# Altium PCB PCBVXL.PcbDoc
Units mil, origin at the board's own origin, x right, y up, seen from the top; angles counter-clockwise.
Board outline 3800 x 3375 mil, 2 copper layers (Top Layer, Bottom Layer); 16 components, 11 nets, 91 pads, 0 vias.
Unrouted connection lines stored in the file: 1.
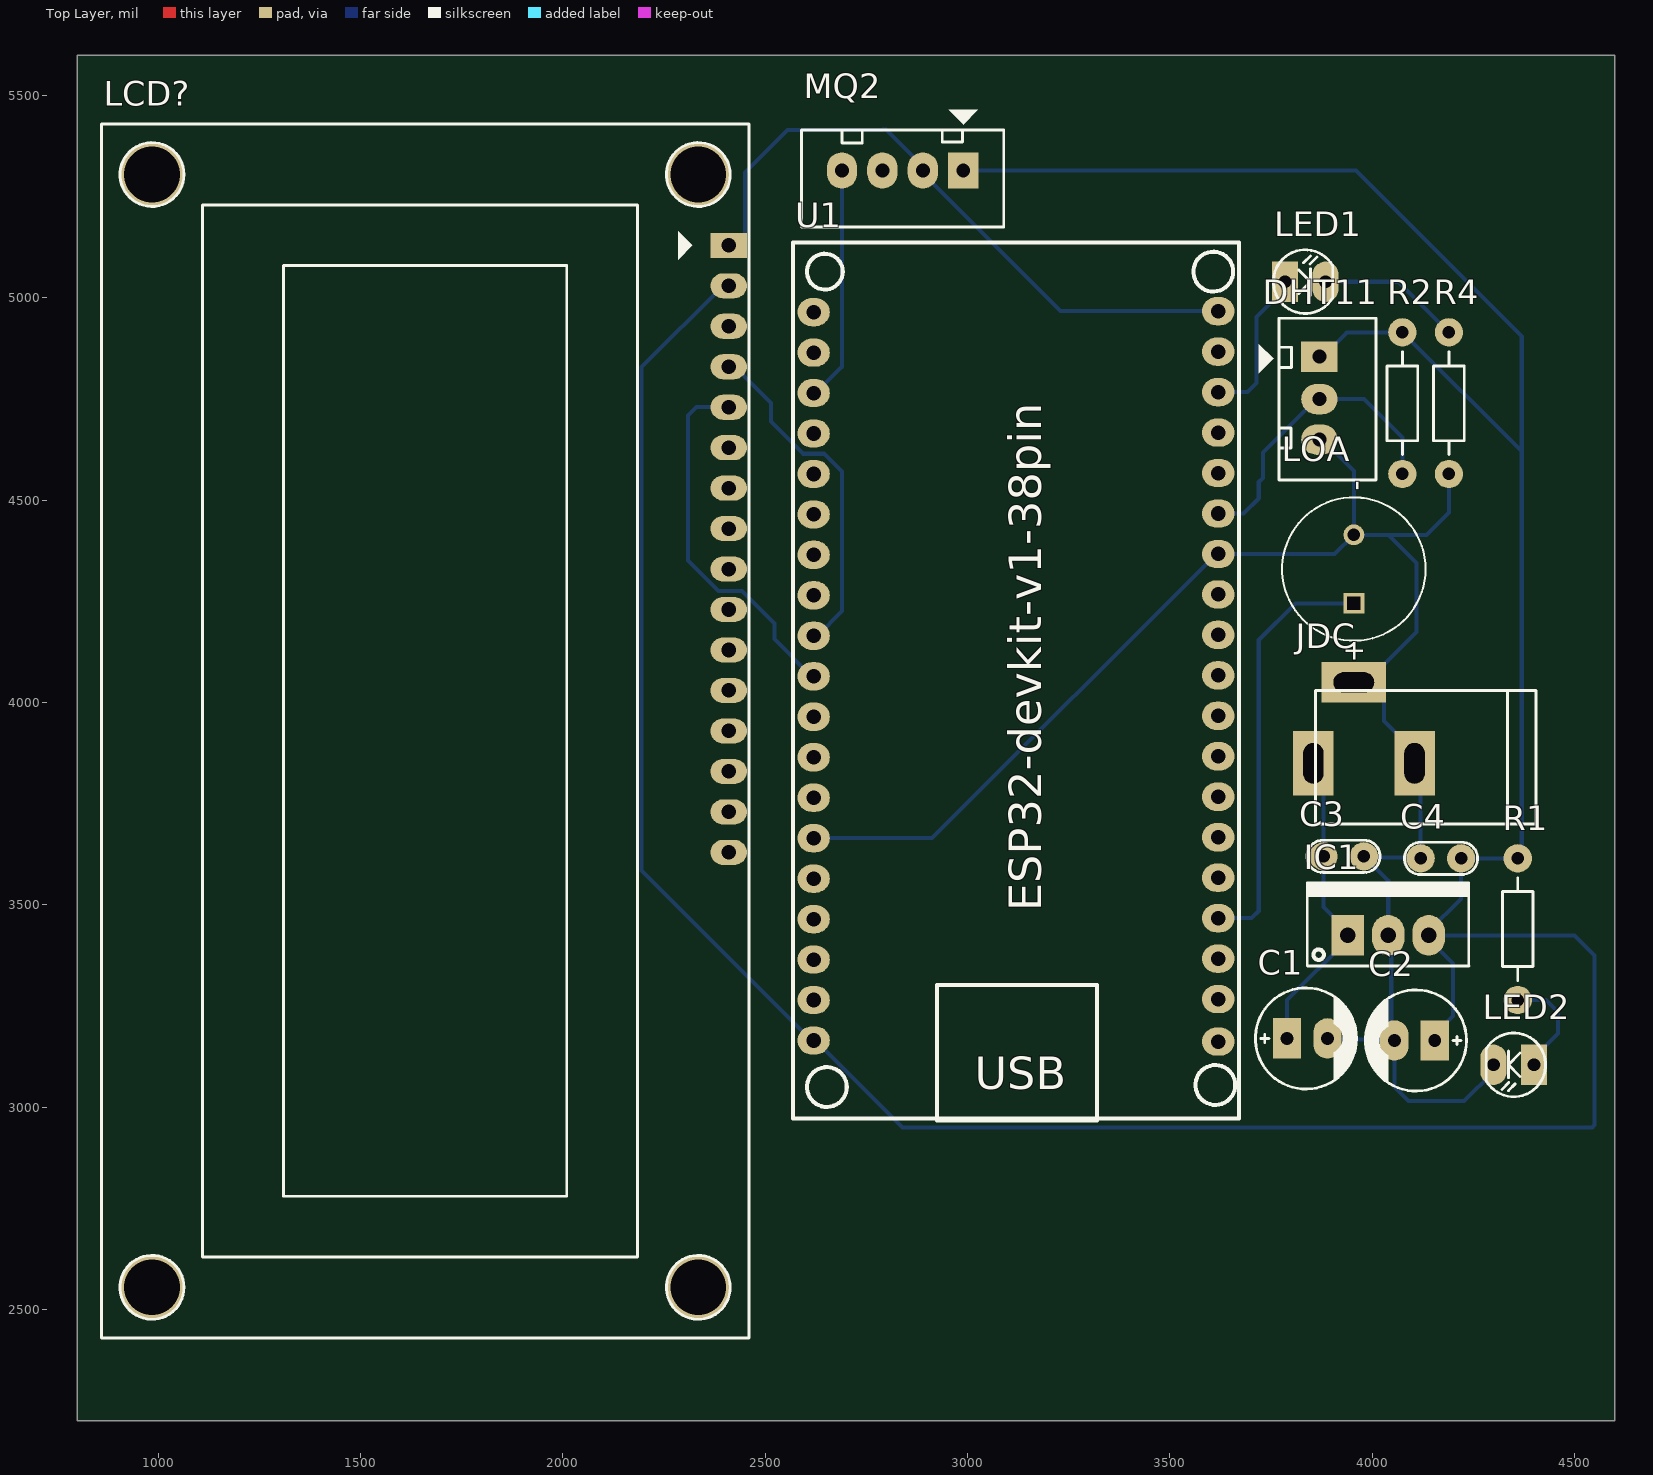
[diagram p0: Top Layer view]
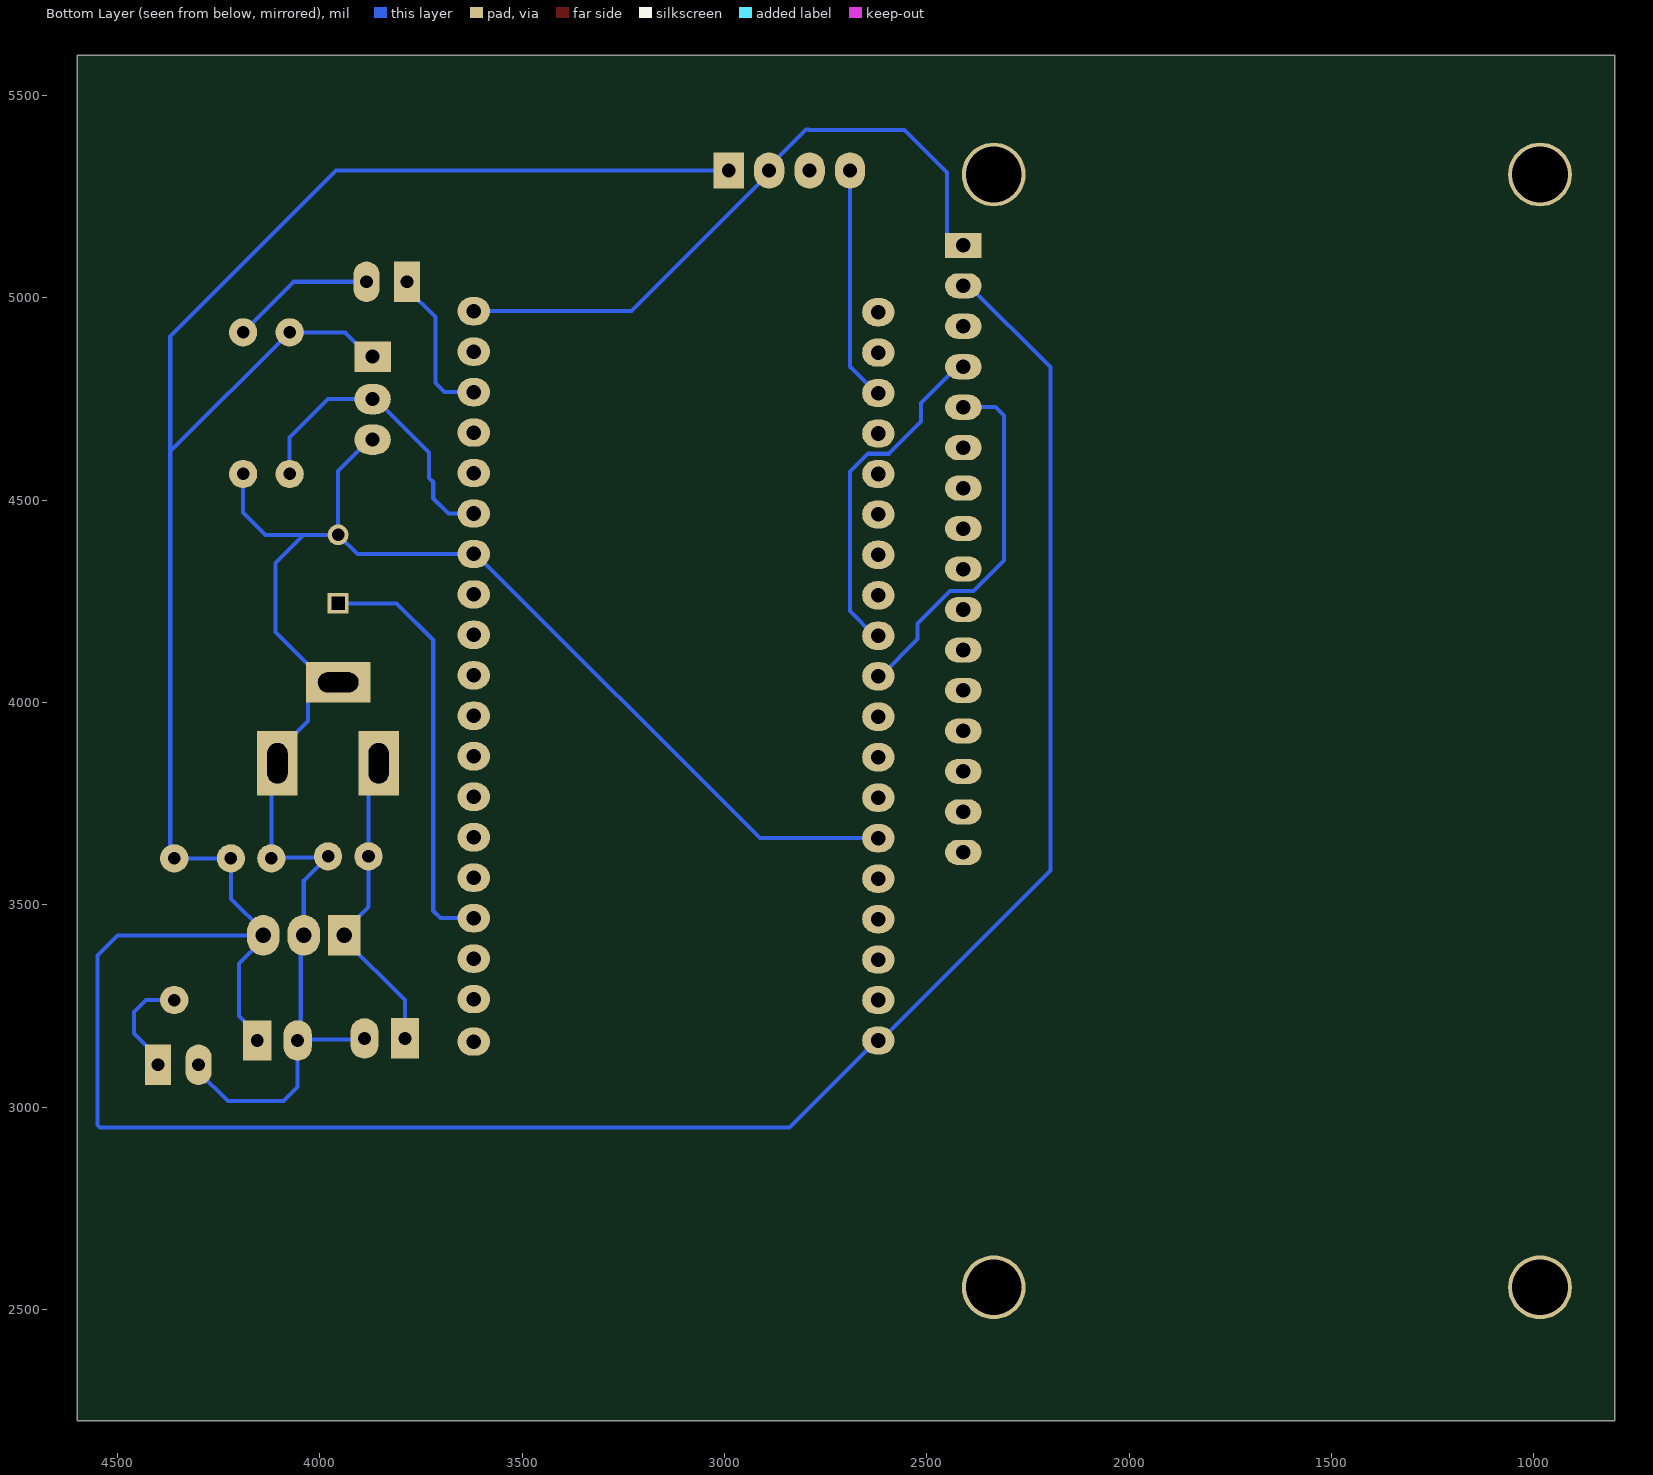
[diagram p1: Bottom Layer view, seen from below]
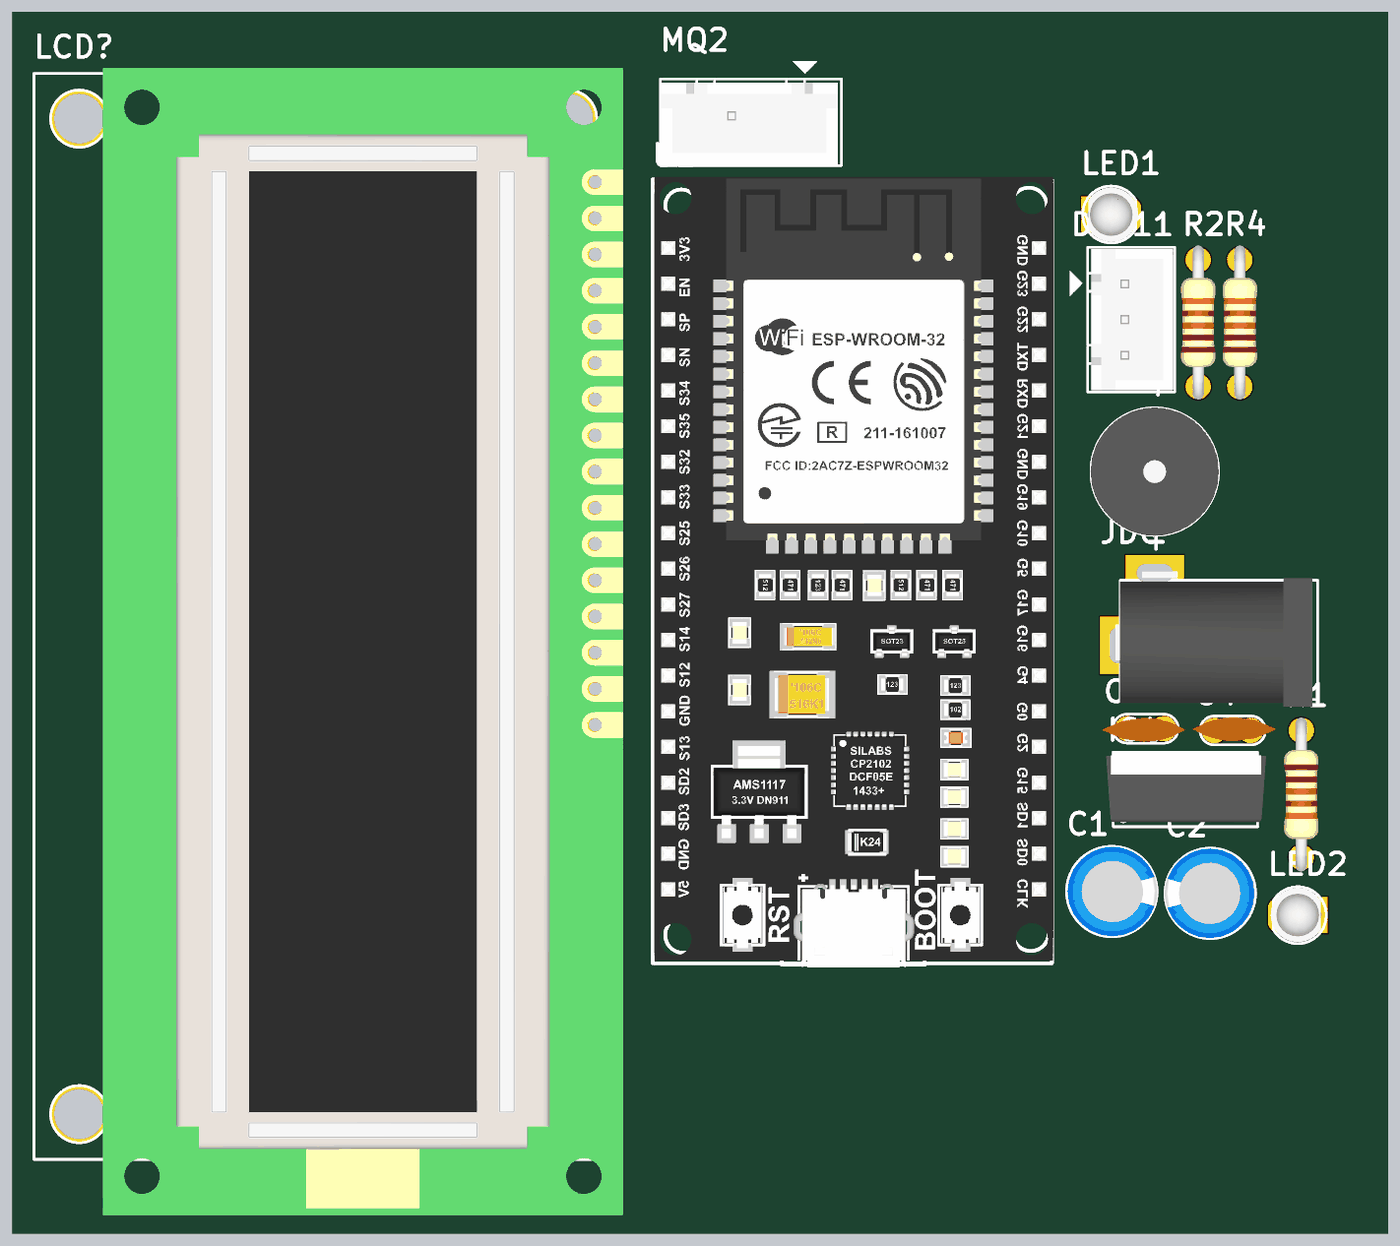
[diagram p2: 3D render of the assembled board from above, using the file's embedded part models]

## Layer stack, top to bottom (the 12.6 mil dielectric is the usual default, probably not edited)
Top Solder: solder mask 0.4, Solder Resist, Dk 3.5
Top Layer: signal copper 1.4
Dielectric 1: dielectric 12.6, FR-4, Dk 4.8
Bottom Layer: signal copper 1.4
Bottom Solder: solder mask 0.4, Solder Resist, Dk 3.5

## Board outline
800,2225 4600,2225 4600,5600 800,5600

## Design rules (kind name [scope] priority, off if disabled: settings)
Clearance [All] p1: gap=10 ignorepadtopadclearanceinfootprint=FALSE except(0: Arc-Hole Track-Hole SMDPad-Hole THPad-Hole Via-Hole Fill-Hole Poly-Hole Region-Hole Text-Hole)
PolygonConnect [All] p1: connectstyle=Relief reliefconductorwidth=10 reliefentries=4 polygonreliefangle="90 Angle" airgapwidth=10
RoutingVias [All] p1: holewidth=28 width=50 viastyle="Through Hole" minholewidth=28 minwidth=50 maxholewidth=28 maxwidth=50
SolderMaskExpansion [All] p1: expansion=4 istentingtop=FALSE
Width [All] p1: maxlimit=10 minlimit=10 preferedwidth=10
30 further rules are at their usual default settings.

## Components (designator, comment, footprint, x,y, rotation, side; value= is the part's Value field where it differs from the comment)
C1 "100uF/35V" CP1/2.5 3790,3170 r0 top value="47uF/16 - 50V"
C2 "47uF/16V" CP1/2.5 4155,3165 r180 top value="47uF/16 - 50V"
C3 "104" CN1 3980,3620 r180 top value=100pF
C4 "104" CN1 4120,3615 r0 top value=100pF
DHT11 "Header3" Header3 3870,4850 r270 top
IC1 "LM7805" QTO-220 3940,3425 r0 top
JDC "Jac DC" DC-IN 3980,3950 r180 top
LCD? "LCD16x2A" LCD16X2 2410,5130 r270 top
LED1 "LED" LED-3 3785,5040 r0 top value="LED 3 ly Single Colour"
LED2 "LED" LED-3 4400,3105 r180 top value="LED 3 ly Single Colour"
LOA "Buzzer" Buzzer-9MM 3955,4330 r90 top
MQ2 "Header4" Header4 2990,5315 r180 top
R1 "1k" R1/4W 4360,3265 r90 top value="R1/4W - 1K"
R2 "1k" R1/4W 4075,4915 r270 top value="R1/4W - 1K"
R4 "1k" R1/4W 4190,4915 r270 top value="R1/4W - 1K"
U1 "ESP32-DEVKI-V1.0-PIN38" ESP32-DEVKIT-V1.0-38PIN 3120,4052.41 r0 top

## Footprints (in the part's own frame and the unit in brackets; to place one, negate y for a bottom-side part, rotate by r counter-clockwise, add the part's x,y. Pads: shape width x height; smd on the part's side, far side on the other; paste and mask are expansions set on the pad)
Buzzer-9MM [mm] "9MM"
  rect 1.308x1.308 hole 0.8 square: 1(-2.15,0)
  round 1.308 hole 0.8: 2(2.15,0)
  silkscreen extent -4.5,-4.5 4.5,4.5, body extent -4.5,-4.5 4.5,4.5, height 4.5
CN1 [mil]
  round 70 hole 31: 1(0,0) 2(100,0)
  silkscreen extent -40,-40 141,40, body extent -60,-30 170,37, height 265
CP1/2.5 [mil] "Tu hoa 33 >100 uF,50V, 220uF/16V,25V"
  rect 70x100 hole 32: 1(0,0)
  oval 70x100 hole 32: 2(100,0)
  silkscreen extent -78,-125 172,125, body extent -76,-124 172,124, height 422
DC-IN [mil] "Jac DC input"
  rect 100x160 hole 50 slot 100 at 90 deg: 1(125,100) 2(-125,100)
  rect 160x100 hole 50 slot 100 at 0 deg: 3(25,-100)
  silkscreen extent -425,-80 120,250, body extent -410,-105 134,269, height 434
ESP32-DEVKIT-V1.0-38PIN [mil] "DEVKIT 38 PIN"
  oval 80x70 hole 36: 1(-500,912.59) 2(-500,812.59) 3(-500,712.59) 4(-500,612.59) 5(-500,512.59) 6(-500,412.59) 7(-500,312.59) 8(-500,212.59) 9(-500,112.59) 10(-500,12.59) 11(-500,-87.41) 12(-500,-187.41) 13(-500,-287.41) 14(-500,-387.41) 15(-500,-487.41) 16(-500,-587.41) 17(-500,-687.41) 18(-500,-787.41) 19(-500,-887.41) 20(500,-890.09) 21(500,-785.09) 22(500,-685.09) 23(500,-585.09) 24(500,-485.09) 25(500,-385.09) 26(500,-285.09) 27(500,-185.09) 28(500,-85.09) 29(500,14.91) 30(500,114.91) 31(500,214.91) 32(500,314.91) 33(500,414.91) 34(500,514.91) 35(500,614.91) 36(500,714.91) 37(500,814.91) 38(500,914.91)
  silkscreen extent -551,-1085 551,1085, body extent -547,-1092 555,1092, height 269
Header3 [mil] "CON 3"
  rect 75x90 hole 34: 1(-5,0)
  oval 75x90 hole 34: 2(100,0) 3(200,0)
  silkscreen extent -100,-150 300,140, body extent -95,-90 295,136, height 276
Header4 [mil] "CON4"
  rect 75x90 hole 34: 1(0,0)
  oval 75x90 hole 34: 2(100,0) 3(200,0) 4(300,0)
  silkscreen extent -100,-150 400,140, body extent -90,-90 398,136, height 276
LCD16X2 [mil] "LCD dipslay 16x2, 16 pin"
  rect 62x90 hole 36: 1(0,0)
  oval 62x90 hole 36: 2(100,0) 3(200,0) 4(300,0) 5(400,0) 6(500,0) 7(600,0) 8(700,0) 9(800,0) 10(900,0) 11(1000,0) 12(1100,0) 13(1200,0) 14(1300,0) 15(1400,0) 16(1500,0)
  round 157.48 hole 137.8: "Hole 0"(-175,-75) "Hole 0"(-175,-1425) "Hole 0"(2575,-75) "Hole 0"(2575,-1425)
  silkscreen extent -300,-1550 2700,50, body extent -315,-1360 2855,77, height 414
LED-3 [mil] "LED 2 PIN, 3ly Only colour"
  rect 65x100 hole 32: 1(0,0)
  oval 65x100 hole 32: 2(100,0)
  silkscreen extent -29,-78 118,79, body extent -13,-75 125,75, height 217
QTO-220 [mil] "TO-220 - 1-2-3"
  rect 80x100 hole 39: 1(0,0)
  oval 80x100 hole 39: 2(100,0) 3(200,0)
  silkscreen extent -100,-76 300,130, body extent -119,-64 322,121, height 755
R1/4W [mil] "R 1/4W, 2 Pin, 350mil"
  round 70 hole 31: 1(0,0) 2(350,0)
  silkscreen extent 48,-38 302,38, body extent -40,-47 386,47, height 111

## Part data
C1 C2: library part CP2, "C 47uF/50V , 220uF/16V"
C3 C4: library part CN1, "Cap np  1pF - 472pF"
DHT11: "Header IDC, 3 x 1 Pin Vertical 2.54mm Pitch (Non-Boxed, Male)", Manufacturer="W¨¹rth Elektronik eiSos GmbH", partNo=613002143121
IC1: library part LM78xx, "On ap +, from + 5 to + 24VDC"
JDC: library part DCIN, "Jac DC input"
LCD?: library part LCD16x2, "LCD dipslay 16 char, 2 line"
LED1 LED2: "LED Single colour Green and Red"
LOA: Package=None
MQ2: "Header IDC, 4 x 1 Pin Vertical 2.54mm Pitch (Non-Boxed, Male)", Manufacturer="W¨¹rth Elektronik eiSos GmbH", partNo=613002143121
R1 R2 R4: library part R1/4W, "Resistor 1/4W"

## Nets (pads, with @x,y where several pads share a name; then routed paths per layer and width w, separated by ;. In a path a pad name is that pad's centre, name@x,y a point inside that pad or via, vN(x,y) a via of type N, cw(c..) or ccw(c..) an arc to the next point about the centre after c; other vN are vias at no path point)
+5: C2.1 C4.2 DHT11.1 IC1.3 LCD?.2 MQ2.1 R1.2 R2.1 U1.19 | length 9170.2
  Bottom Layer w10: LCD?.2 2396,5030 2195,4829 2195,3585 2615,3165 U1.19 2625,3165 2840,2950 4544.14,2950 4550,2955.86 4550,3375 4500,3425 IC1.3 ; MQ2.1 3960,5315 4370,4905 4370,4620 ; DHT11.1 3877.5,4855 3937.5,4915 R2.1 4370,4620 ; C2.1 4155,3180 4200,3225 4200,3355 4140,3415 IC1.3 ; IC1.3 4140,3435 4220,3515 C4.2 R1.2 4370,3625 4370,4620
buzzer: LOA.1 U1.23 | length 1049.7
  Bottom Layer w10: U1.23 3702.32,3467.32 3720,3485 3720,4155 3810.35,4245.35 LOA.1
DHT11: DHT11.2 R2.2 U1.33 | length 761.5
  Bottom Layer w10: U1.33 3682.32,4467.32 3720,4505 3720,4545 3730,4555 3730,4617.5 3862.5,4750 DHT11.2 3980,4750 4075,4655 R2.2
GND: C1.2 C2.2 C3.1 C4.1 DHT11.3 IC1.2 JDC.2 JDC.3 LCD?.1 LED2.2 LOA.2 MQ2.2 R4.2 U1.14 U1.32 U1.38 | length 6064.4
  Bottom Layer w10: LCD?.1 2424,5130 2450,5156 2450,5310 2555,5415 2790,5415 2790.86,5415.86 2799.14,5415.86 2890,5325 MQ2.2 2890,5307.5 3230.18,4967.32 U1.38 ; U1.14 2912.68,3665 3615,4367.32 U1.32 3907.68,4367.32 LOA.2 ; DHT11.3 3877.5,4650 3955,4572.5 LOA.2 ; C1.2 3892.5,3167.5 C2.2@4052.5,3167.5 ; JDC.3 JDC.3@3985,4050 ; C3.1 C3.1@3982.5,3617.5 ; R4.2 4190,4470 4134.65,4414.65 4040.35,4414.65 ; LED2.2 4300,3087.5 4227.5,3015 4090,3015 4055,3050 C2.2 C2.2@4052.5,3167.5 ; LOA.2 4040.35,4414.65 ; C3.1@3982.5,3617.5 4040,3560 IC1.2 4047.5,3417.5 4047.5,3172.5 C2.2@4052.5,3167.5 ; C3.1@3982.5,3617.5 4117.5,3617.5 C4.1 4120,3835 JDC.2 4105,3880 4030,3955 4030,4005 JDC.3@3985,4050 ; JDC.3@3985,4050 4110,4175 4110,4345 4040.35,4414.65
LED: LED1.1 U1.36 | length 383.4
  Bottom Layer w10: U1.36 3692.32,4767.32 3715,4790 3715,4952.5 3785,5022.5 LED1.1
MQ2: MQ2.4 U1.3 | length 581.9
  Bottom Layer w10: U1.3 2625,4765 2690,4830 MQ2.4
NetC1_1: C1.1 C3.2 IC1.1 JDC.1 | length 777.3
  Bottom Layer w10: C1.1 3790,3265 3940,3415 IC1.1 3940,3435 3880,3495 C3.2 3880,3825 JDC.1
NetLED1_2: LED1.2 R4.1 | length 356.8
  Bottom Layer w10: LED1.2 4065,5040 R4.1
NetLED2_1: LED2.1 R1.1 | length 267.3
  Bottom Layer w10: R1.1 4430,3265 4460,3235 4460,3182.5 4400,3122.5 LED2.1
SCL: LCD?.5 U1.10 | length 918.2
  Bottom Layer w10: LCD?.5 2330.86,4730 2310,4709.14 2310,4350.95 2384.95,4276 2443.05,4276 2523.29,4195.77 2523.29,4156.71 2615,4065 U1.10
SDA: LCD?.4 U1.9 | length 853.7
  Bottom Layer w10: LCD?.4 2424,4830 2514.12,4739.88 2514.12,4695.17 2594.29,4615 2645.71,4615 2690,4570.71 2690,4225.86 2629.14,4165 U1.9
pads on no net: "LCD?.Hole 0" LCD?.3 LCD?.6 LCD?.7 LCD?.8 LCD?.9 LCD?.10 LCD?.11 LCD?.12 LCD?.13 LCD?.14 LCD?.15 LCD?.16 MQ2.3 U1.1 U1.2 U1.4 U1.5 U1.6 U1.7 U1.8 U1.11 U1.12 U1.13 U1.15 U1.16 U1.17 U1.18 U1.20 U1.21 U1.22 U1.24 U1.25 U1.26 U1.27 U1.28 U1.29 U1.30 U1.31 U1.34 U1.35 U1.37

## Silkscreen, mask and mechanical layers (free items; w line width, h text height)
Mechanical 1:
  the board outline again, w19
